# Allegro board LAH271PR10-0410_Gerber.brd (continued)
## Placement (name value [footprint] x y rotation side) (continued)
PC1231  10U_0805_25VAK  [C_0805]  234.88 144.32 90 top
PC1232  10U_0805_25VAK  [C_0805]  236.59 144.33 90 top
PC1233  0.22U_0603_25V7K  [C_0603]  232.3 142.19 270 top
PC1234  1U_0603_16V7K  [C_0603]  236.15 142.1 180 top
PC1235  2.2U_0603_10V7K  [C_0603]  237.27 140.83 90 top
PC1236  1000P_0603_50V7K  [C_0603]  236.96 133.08 90 bottom
PC1237  2200P_0402_50V7K  [C_0402]  219.74 135.14 270 top
PC1238  0.1U_0402_25V7K  [C_0402]  219.74 135.14 270 bottom
PC1239  10U_0805_25VAK  [C_0805]  222.79 135.71 270 bottom
PC1240  10U_0805_25VAK  [C_0805]  221.07 135.7 270 bottom
PC1241  10U_0805_25VAK  [C_0805]  222.79 135.71 270 top
PC1242  10U_0805_25VAK  [C_0805]  221.07 135.7 270 top
PC1243  0.22U_0603_25V7K  [C_0603]  224.53 139.71 270 top
PC1244  1U_0603_16V7K  [C_0603]  228.25 139.6 180 top
PC1245  2.2U_0603_10V7K  [C_0603]  229.35 138.34 90 top
PC1246  1000P_0603_50V7K  [C_0603]  229.11 130.62 90 bottom
PC1300  330U_D2_2.5V_R6M  [C_D2]  233.57 125.05 90 bottom
PC1301  330U_D2_2.5V_R6M  [C_D2]  241.07 125.1 90 bottom
PC1302  22U_0603_6.3VAM  [C_0603]  226.7 104.99 0 bottom
PC1303  22U_0603_6.3VAM  [C_0603]  226.7 103.77 0 bottom
PC1304  22U_0603_6.3VAM  [C_0603]  229.06 104.99 0 bottom
PC1305  22U_0603_6.3VAM  [C_0603]  229.06 103.77 0 bottom
PC1306  22U_0603_6.3VAM  [C_0603]  240.87 121.25 0 bottom
PC1307  22U_0603_6.3VAM  [C_0603]  244.11 121.25 0 bottom
PC1308  22U_0603_6.3VAM  [C_0603]  236.73 99.83 0 bottom
PC1309  22U_0603_6.3VAM  [C_0603]  240.87 122.47 0 bottom
PC1310  22U_0603_6.3VAM  [C_0603]  244.11 122.47 0 top
PC1311  22U_0603_6.3VAM  [C_0603]  237.47 122.47 0 bottom
PC1312  22U_0603_6.3VAM  [C_0603]  234.16 122.42 0 bottom
PC1313  22U_0603_6.3VAM  [C_0603]  230.76 122.42 0 bottom
PC1314  22U_0603_6.3VAM  [C_0603]  244.11 122.47 0 bottom
PC1315  22U_0603_6.3VAM  [C_0603]  237.47 122.47 0 top
PC1316  22U_0603_6.3VAM  [C_0603]  234.16 122.42 0 top
PC1317  22U_0603_6.3VAM  [C_0603]  230.76 122.42 0 top
PC1318  22U_0603_6.3VAM  [C_0603]  240.87 122.47 0 top
PC1319  22U_0603_6.3VAM  [C_0603]  228.61 99.88 0 bottom
PC1320  22U_0603_6.3VAM  [C_0603]  232.42 99.88 180 bottom
PC1321  22U_0603_6.3VAM  [C_0603]  229.06 102.55 0 bottom
PC1322  22U_0603_6.3VAM  [C_0603]  226.71 102.55 0 bottom
PC1323  22U_0603_6.3VAM  [C_0603]  233.44 99.88 0 bottom
PC1324  10U_0402_6.3VAM  [C_0402]  232 98.74 180 bottom
PC1325  10U_0402_6.3VAM  [C_0402]  227.61 98.86 180 bottom
PC1326  10U_0402_6.3VAM  [C_0402]  228.93 98.76 0 bottom
PC1327  10U_0402_6.3VAM  [C_0402]  236.37 98.74 180 bottom
PC1328  10U_0402_6.3VAM  [C_0402]  233.42 98.74 0 bottom
PC1329  10U_0402_6.3VAM  [C_0402]  237.23 98.74 0 bottom
PC1330  10U_0402_6.3VAM  [C_0402]  227.61 99.88 180 bottom
PC1331  10U_0402_6.3VAM  [C_0402]  233.51 106.05 180 bottom
PC1332  10U_0402_6.3VAM  [C_0402]  234.34 106.94 0 bottom
PC1333  10U_0402_6.3VAM  [C_0402]  234.34 106.05 0 bottom
PC1334  10U_0402_6.3VAM  [C_0402]  236.07 106.94 0 bottom
PC1335  10U_0402_6.3VAM  [C_0402]  236.07 106.05 0 bottom
PC1336  10U_0402_6.3VAM  [C_0402]  238.72 106.94 180 bottom
PC1337  10U_0402_6.3VAM  [C_0402]  238.72 106.05 180 bottom
PC1338  10U_0402_6.3VAM  [C_0402]  227.36 106.94 0 bottom
PC1339  10U_0402_6.3VAM  [C_0402]  227.36 106.05 0 bottom
PC1340  10U_0402_6.3VAM  [C_0402]  229.11 106.05 0 bottom
PC1341  10U_0402_6.3VAM  [C_0402]  229.11 106.94 0 bottom
PC1342  10U_0402_6.3VAM  [C_0402]  231.77 106.94 180 bottom
PC1343  10U_0402_6.3VAM  [C_0402]  231.77 106.05 180 bottom
PC1344  10U_0402_6.3VAM  [C_0402]  233.51 106.94 180 bottom
PC1345  1U_0201_6.3VAM  [C_0201]  227.19 97.34 180 bottom
PC1346  1U_0201_6.3VAM  [C_0201]  227.15 108.77 0 bottom
PC1347  1U_0201_6.3VAM  [C_0201]  227.15 108.21 0 bottom
PC1348  1U_0201_6.3VAM  [C_0201]  227.19 97.98 180 bottom
PC1349  1U_0201_6.3VAM  [C_0201]  227.87 97.98 0 bottom
PC1350  1U_0201_6.3VAM  [C_0201]  231.51 97.98 0 bottom
PC1351  1U_0201_6.3VAM  [C_0201]  231.51 97.34 0 bottom
PC1352  1U_0201_6.3VAM  [C_0201]  233.36 97.98 180 bottom
PC1353  1U_0201_6.3VAM  [C_0201]  233.36 97.34 180 bottom
PC1354  1U_0201_6.3VAM  [C_0201]  229.07 97.98 0 bottom
PC1355  1U_0201_6.3VAM  [C_0201]  229.07 97.34 0 bottom
PC1356  1U_0201_6.3VAM  [C_0201]  230.87 97.98 180 bottom
PC1357  1U_0201_6.3VAM  [C_0201]  230.87 97.34 180 bottom
PC1358  1U_0201_6.3VAM  [C_0201]  238.75 97.98 180 bottom
PC1359  1U_0201_6.3VAM  [C_0201]  238.75 97.34 180 bottom
PC1360  1U_0201_6.3VAM  [C_0201]  234 97.34 0 bottom
PC1361  1U_0201_6.3VAM  [C_0201]  234 97.98 0 bottom
PC1362  1U_0201_6.3VAM  [C_0201]  235.95 97.98 180 bottom
PC1363  1U_0201_6.3VAM  [C_0201]  235.92 97.36 180 bottom
PC1364  1U_0201_6.3VAM  [C_0201]  236.89 97.34 0 bottom
PC1365  1U_0201_6.3VAM  [C_0201]  236.89 97.98 0 bottom
PC1366  1U_0201_6.3VAM  [C_0201]  243.1 108.13 180 bottom
PC1367  1U_0201_6.3VAM  [C_0201]  240.73 108.77 180 bottom
PC1368  1U_0201_6.3VAM  [C_0201]  240.73 108.21 180 bottom
PC1369  1U_0201_6.3VAM  [C_0201]  241.33 108.77 0 bottom
PC1370  1U_0201_6.3VAM  [C_0201]  241.33 108.21 0 bottom
PC1371  1U_0201_6.3VAM  [C_0201]  227.87 97.34 0 bottom
PC1372  1U_0201_6.3VAM  [C_0201]  243.1 108.69 180 bottom
PC1373  1U_0201_6.3VAM  [C_0201]  238.95 108.77 0 bottom
PC1374  1U_0201_6.3VAM  [C_0201]  238.95 108.21 0 bottom
PC1375  1U_0201_6.3VAM  [C_0201]  238.37 108.77 180 bottom
PC1376  1U_0201_6.3VAM  [C_0201]  238.37 108.21 180 bottom
PC1377  1U_0201_6.3VAM  [C_0201]  236.61 108.77 0 bottom
PC1378  1U_0201_6.3VAM  [C_0201]  236.61 108.21 0 bottom
PC1379  1U_0201_6.3VAM  [C_0201]  236 108.77 180 bottom
PC1380  1U_0201_6.3VAM  [C_0201]  236 108.21 180 bottom
PC1381  1U_0201_6.3VAM  [C_0201]  233.64 108.77 180 bottom
PC1382  1U_0201_6.3VAM  [C_0201]  233.64 108.21 180 bottom
PC1383  1U_0201_6.3VAM  [C_0201]  231.87 108.77 0 bottom
PC1384  1U_0201_6.3VAM  [C_0201]  231.87 108.21 0 bottom
PC1385  1U_0201_6.3VAM  [C_0201]  231.28 108.21 180 bottom
PC1386  1U_0201_6.3VAM  [C_0201]  231.28 108.77 180 bottom
PC1387  1U_0201_6.3VAM  [C_0201]  234.25 108.21 0 bottom
PC1388  1U_0201_6.3VAM  [C_0201]  234.25 108.77 0 bottom
PC1389  1U_0201_6.3VAM  [C_0201]  229.51 108.21 0 bottom
PC1390  1U_0201_6.3VAM  [C_0201]  229.51 108.77 0 bottom
PC1391  1U_0201_6.3VAM  [C_0201]  228.92 108.77 180 bottom
PC1392  1U_0201_6.3VAM  [C_0201]  228.92 108.21 180 bottom
PC1393  330U_D2_2.5V_R6M  [C_D2]  225.47 122.6 90 bottom
PC1394  330U_D2_2.5V_R6M  [C_D2]  241.63 105.18 270 bottom
PC1395  22U_0603_6.3VAM  [C_0603]  230.77 121.19 0 bottom
PC1396  22U_0603_6.3VAM  [C_0603]  234.16 121.19 0 bottom
PC1397  22U_0603_6.3VAM  [C_0603]  237.48 121.24 0 bottom
PC1398  22U_0603_6.3VAM  [C_0603]  234.15 119.98 0 bottom
PC1399  22U_0603_6.3VAM  [C_0603]  237.51 119.97 0 bottom
PC1400  22U_0603_6.3VAM  [C_0603]  240.88 120.01 0 bottom
PC1401  10U_0402_6.3VAM  [C_0402]  235.77 102.34 0 bottom
PC1402  10U_0402_6.3VAM  [C_0402]  233.6 101.5 0 bottom
PC1403  10U_0402_6.3VAM  [C_0402]  235.79 101.42 0 bottom
PC1404  10U_0402_6.3VAM  [C_0402]  227.58 100.83 180 bottom
PC1405  10U_0402_6.3VAM  [C_0402]  232.76 101.5 180 bottom
PC1406  10U_0402_6.3VAM  [C_0402]  238.79 101.4 180 bottom
PC1407  10U_0402_6.3VAM  [C_0402]  232.76 102.41 180 bottom
PC1408  10U_0402_6.3VAM  [C_0402]  235.78 103.25 0 bottom
PC1409  10U_0402_6.3VAM  [C_0402]  233.6 102.4 0 bottom
PC1410  10U_0402_6.3VAM  [C_0402]  232.77 104.24 180 bottom
PC1411  10U_0402_6.3VAM  [C_0402]  235.77 104.16 0 bottom
PC1412  10U_0402_6.3VAM  [C_0402]  238.77 102.33 180 bottom
PC1413  10U_0402_6.3VAM  [C_0402]  238.79 103.24 180 bottom
PC1414  10U_0402_6.3VAM  [C_0402]  235.78 105.07 0 bottom
PC1415  10U_0402_6.3VAM  [C_0402]  238.77 104.16 180 bottom
PC1416  10U_0402_6.3VAM  [C_0402]  233.58 105.14 0 bottom
PC1417  10U_0402_6.3VAM  [C_0402]  232.76 105.13 180 bottom
PC1418  10U_0402_6.3VAM  [C_0402]  238.78 105.06 180 bottom
PC1419  10U_0402_6.3VAM  [C_0402]  233.59 104.23 0 bottom
PC1420  10U_0402_6.3VAM  [C_0402]  233.59 103.31 0 bottom
PC1421  10U_0402_6.3VAM  [C_0402]  232.77 103.32 180 bottom
PC1500  470U_X_2VM_R6M  [C_X]  254.8 122.91 0 bottom
PC1502  22U_0603_6.3VAM  [C_0603]  253.09 106.73 180 bottom
PC1503  22U_0603_6.3VAM  [C_0603]  253.08 105.52 180 bottom
PC1504  22U_0603_6.3VAM  [C_0603]  253.09 104.31 180 bottom
PC1505  22U_0603_6.3VAM  [C_0603]  249.34 100.62 0 bottom
PC1506  22U_0603_6.3VAM  [C_0603]  246.02 106.73 180 bottom
PC1507  22U_0603_6.3VAM  [C_0603]  246.02 105.52 180 bottom
PC1508  22U_0603_6.3VAM  [C_0603]  246.02 104.31 180 bottom
PC1509  22U_0603_6.3VAM  [C_0603]  246.99 106.73 0 bottom
PC1510  22U_0603_6.3VAM  [C_0603]  246.99 105.52 0 bottom
PC1511  22U_0603_6.3VAM  [C_0603]  246.99 104.31 0 bottom
PC1512  22U_0603_6.3VAM  [C_0603]  250.74 104.31 180 bottom
PC1513  22U_0603_6.3VAM  [C_0603]  250.74 105.52 180 bottom
PC1514  22U_0603_6.3VAM  [C_0603]  250.74 106.73 180 bottom
PC1515  10U_0402_6.3VAM  [C_0402]  247.3 108.68 180 bottom
PC1516  10U_0402_6.3VAM  [C_0402]  247.3 107.77 180 bottom
PC1517  10U_0402_6.3VAM  [C_0402]  248.14 108.68 0 bottom
PC1518  10U_0402_6.3VAM  [C_0402]  248.14 107.78 0 bottom
PC1519  10U_0402_6.3VAM  [C_0402]  253.15 107.77 180 bottom
PC1520  10U_0402_6.3VAM  [C_0402]  253.15 108.67 180 bottom
PC1521  10U_0402_6.3VAM  [C_0402]  249.29 98.41 0 bottom
PC1522  10U_0402_6.3VAM  [C_0402]  251.96 98.41 180 bottom
PC1523  10U_0402_6.3VAM  [C_0402]  249.29 97.47 0 bottom
PC1524  10U_0402_6.3VAM  [C_0402]  251.96 97.47 180 bottom
PC1525  1U_0201_6.3VAM  [C_0201]  244.5 108.7 180 bottom
PC1526  1U_0201_6.3VAM  [C_0201]  244.5 108.14 180 bottom
PC1527  1U_0201_6.3VAM  [C_0201]  245.1 108.84 0 bottom
PC1528  1U_0201_6.3VAM  [C_0201]  245.1 108.27 0 bottom
PC1529  1U_0201_6.3VAM  [C_0201]  250.34 108.79 180 bottom
PC1530  1U_0201_6.3VAM  [C_0201]  250.34 108.22 180 bottom
PC1531  1U_0201_6.3VAM  [C_0201]  250.94 108.79 0 bottom
PC1532  1U_0201_6.3VAM  [C_0201]  250.94 108.22 0 bottom
PC1533  1U_0201_6.3VAM  [C_0201]  245.52 97.63 180 bottom
PC1534  1U_0201_6.3VAM  [C_0201]  246.16 97.63 0 bottom
PC1535  1U_0201_6.3VAM  [C_0201]  249.34 99.4 0 bottom
PC1536  1U_0201_6.3VAM  [C_0201]  253.09 100.62 180 bottom
PC1600  22U_0603_6.3VAM  [C_0603]  226.21 107.92 270 bottom
PC1601  22U_0603_6.3VAM  [C_0603]  220.72 119.67 90 bottom
PC1602  22U_0603_6.3VAM  [C_0603]  211.98 125.18 180 bottom
PC1603  22U_0603_6.3VAM  [C_0603]  211.99 123.97 180 bottom
PC1604  22U_0603_6.3VAM  [C_0603]  221.95 119.68 90 bottom
PC1605  22U_0603_6.3VAM  [C_0603]  211.98 122.77 180 bottom
PC1606  22U_0603_6.3VAM  [C_0603]  211.98 125.48 180 top
PC1607  22U_0603_6.3VAM  [C_0603]  211.99 124.28 180 top
PC1608  22U_0603_6.3VAM  [C_0603]  211.98 123.07 180 top
PC1609  22U_0603_6.3VAM  [C_0603]  219.49 119.66 90 bottom
PC1610  10U_0402_6.3VAM  [C_0402]  223.72 108.83 0 bottom
PC1611  10U_0402_6.3VAM  [C_0402]  226.38 108.83 180 bottom
PC1612  10U_0402_6.3VAM  [C_0402]  224.28 107.94 0 bottom
PC1613  10U_0402_6.3VAM  [C_0402]  211.82 120.02 180 top
PC1614  10U_0402_6.3VAM  [C_0402]  211.83 121.94 180 top
PC1615  10U_0402_6.3VAM  [C_0402]  211.82 120.98 180 top
PC1616  10U_0402_6.3VAM  [C_0402]  211.81 119.08 180 top
PC1617  1U_0201_6.3VAM  [C_0201]  223.04 108.35 270 bottom
PC1700  2200P_0402_50V7K  [C_0402]  268.33 122.91 180 bottom
PC1701  0.1U_0402_25V7K  [C_0402]  268.33 122.91 180 top
PC1702  10U_0603_25V6M  [C_0603]  268.76 121.84 180 top
PC1703  10U_0603_25V6M  [C_0603]  268.76 121.84 180 bottom
PC1704  10U_0603_25V6M  [C_0603]  268.74 120.61 180 top
PC1705  10U_0603_25V6M  [C_0603]  268.74 120.61 180 bottom
PC1706  0.22U_0603_25V7K  [C_0603]  272.24 125.95 180 bottom
PC1707  1U_0603_16V7K  [C_0603]  272.06 129.73 270 bottom
PC1708  2.2U_0603_10V7K  [C_0603]  270.74 130.75 90 bottom
PC1709  1000P_0603_50V7K  [C_0603]  262.97 126 270 bottom
PC1710  10U_0603_25V6M  [C_0603]  271.25 121.78 0 bottom
PC1711  10U_0603_25V6M  [C_0603]  271.2 123.04 0 bottom
PC1712  10U_0603_25V6M  [C_0603]  271.18 124.31 0 bottom
PC1713  10U_0603_25V6M  [C_0603]  269.18 124.18 180 bottom
PC1800  2200P_0402_50V7K  [C_0402]  208.8 130.74 270 top
PC1801  0.1U_0402_25V7K  [C_0402]  208.8 130.74 270 bottom
PC1802  10U_0805_25VAK  [C_0805]  210.11 131.03 270 bottom
PC1803  10U_0805_25VAK  [C_0805]  210.12 131.02 270 top
PC1804  10U_0805_25VAK  [C_0805]  211.86 131 270 top
PC1805  10U_0805_25VAK  [C_0805]  211.85 131.01 270 bottom
PC1806  0.22U_0603_25V7K  [C_0603]  214.26 133.8 270 bottom
PC1807  1U_0603_16V7K  [C_0603]  218.04 132.32 180 bottom
PC1808  2.2U_0603_10V7K  [C_0603]  218.22 129.85 90 bottom
PC1809  1000P_0603_50V7K  [C_0603]  218.39 128.22 270 bottom
PC2100  0.022U_0402_25V7K  [C_0402]  38.32 18.64 270 bottom
PC2102  0.022U_0402_25V7K  [C_0402]  38.2 21.39 270 bottom
PC2103  0.1U_0402_25V6  [C_0402]  39.19 10.34 270 top
PD4  -  [SS5P10-M3-86A_TO277A3]  47.93 10.93 180 top
PD6  -  [SS5P10-M3-86A_TO277A3]  47.95 10.91 0 bottom
PD8  -  [BAS40CW_SOT323-3]  339.85 8.2 180 bottom
PD9  AZ5A25-02R_SOT523-3  [TVNST52302AB0_SOT523-3]  263.6 9.58 180 top
PD10  AZ5A25-02R_SOT523-3  [TVNST52302AB0_SOT523-3]  260.66 7.89 270 top
PD12  BAT54CW-7-F SOT-323  [BAT54CW_SOT323-3]  56.55 14.95 270 top
PD13  BAT54CW-7-F SOT-323  [BAT54CW_SOT323-3]  51.46 14.95 90 top
PD14  BAT54CW-7-F SOT-323  [BAT54CW_SOT323-3]  46.6 25.52 90 top
PD15  BAT54CW-7-F SOT-323  [BAT54CW_SOT323-3]  53.82 9.41 90 bottom
PD200  30MA_30V_0.5UA_0.4V_SOD323-2  [D_SOD323-2]  203.37 6.52 0 top
PD700  BAT54CW-7-F SOT-323  [BAT54CW_SOT323-3]  282.56 36.75 180 top
PD701  BAT54CW-7-F SOT-323  [BAT54CW_SOT323-3]  283.83 40.57 270 top
PD702  -  [MM3Z22VST1G_SOD323-2]  293.07 28.91 270 top
PH1100  100K_0402_1%_TSM0B104F4251RZ  [R_0402]  216.26 120.61 0 top
PH1101  220K_0402_5%_ERTJ0EV224J  [R_0402]  253.45 131.2 90 top
PH1102  220K_0402_5%_ERTJ0EV224J  [R_0402]  261.97 133.23 0 bottom
PH1103  220K_0402_5%_ERTJ0EV224J  [R_0402]  253.72 134.84 90 top
PH1104  220K_0402_5%_ERTJ0EV224J  [R_0402]  265.97 132.03 0 bottom
PJP1  PAD-OPEN1x1m  [JUMP_43X39]  191.42 85.84 90 top
PJP2  PAD-OPEN1x1m  [JUMP_43X39]  191.99 97.31 270 top
PJP3  -  [JUMP_43X79]  199.03 20.6 0 bottom
PJP5  -  [JUMP_43X79]  42.19 30.65 0 top
PJP6  PAD-OPEN1x1m  [JUMP_43X39]  36.57 46.4 180 top
PJP12  PAD-OPEN1x1m  [JUMP_43X39]  96.71 22.76 0 top
PJP17  PAD-OPEN1x2m  [JUMP_43X79]  342.88 36.28 270 top
PJP18  PAD-OPEN1x1m  [JUMP_43X39]  333.94 19.96 90 top
PJP19  PAD-OPEN1x1m  [JUMP_43X39]  356.9 22.6 90 top
PJP20  PAD-OPEN1x1m  [JUMP_43X39]  132.03 14.11 90 top
PJP22  PAD-OPEN1x1m  [JUMP_43X39]  144.86 20.61 180 top
PJP30  -  [JUMP_43X79]  91.4 31.69 270 top
PJP32  PAD-OPEN1x1m  [JUMP_43X39]  326.06 30.91 180 top
PJP35  PAD-OPEN1x1m  [JUMP_43X39]  276.4 3.22 90 top
PJP36  -  [JUMP_43X79]  320.76 25.76 0 top
PJP37  -  [JUMP_43X79]  329.96 23.26 180 top
PJP38  -  [JUMP_43X79]  109.37 27.11 180 bottom
PJP39  -  [JUMP_43X79]  345.48 45.5 180 top
PJP40  PAD-OPEN 4x4m  [JUMP_43X118]  334.04 45.9 0 top
PJP42  -  [JUMP_43X79]  335.99 23.95 180 bottom
PJP43  -  [JUMP_43X79]  184.42 92.04 270 bottom
PJP62  -  [JUMP_43X79]  313.14 14.17 0 top
PJP64  -  [JUMP_43X79]  89.97 21.94 90 top
PJP65  -  [JUMP_43X79]  185.03 82.62 90 bottom
PJP66  -  [JUMP_43X79]  179.58 70.21 0 bottom
PJP67  -  [JUMP_43X118]  104.15 12.5 90 top
PJP69  PAD-OPEN1x2m  [JUMP_43X79]  34.37 12.96 180 bottom
PJP100  PAD-OPEN 1x2m~D  [JUMP_43X79]  116.81 2.72 90 top
PJP101  -  [JUMP_43X118]  97.1 6.33 90 top
PJP102  PAD-OPEN 1x2m~D  [JUMP_43X79]  73.4 11.39 180 bottom
PJP103  -  [JUMP_43X118]  61.07 16.46 180 top
PJP200  PAD-OPEN 1x2m  [JUMP_43X79]  213.84 5.52 90 top
PJP202  JUMP_1x3m  [JUMP_43X118]  245.57 10.25 270 top
PJP203  JUMP_1x3m  [JUMP_43X118]  240.34 10.27 270 top
PJP204  PAD-OPEN1x1m  [JUMP_43X39]  207.91 12.84 180 top
PJP300  -  [JUMP_43X79]  278.34 98.72 270 bottom
PJP301  -  [JUMP_43X118]  268.79 105.62 180 bottom
PJP391  PAD-OPEN1x1m  [JUMP_43X39]  113.88 27.92 90 top
PJP400  -  [JUMP_43X79]  286.72 42.01 90 top
PJP401  -  [JUMP_43X79]  285.96 54.89 90 top
PJP500  PAD-OPEN 1x2m~D  [JUMP_43X79]  315.4 32.84 90 top
PJP501  -  [JUMP_43X118]  295.94 38.53 180 top
PJP502  -  [JUMP_43X118]  297.33 29.04 180 top
PJP503  PAD-OPEN 1x2m~D  [JUMP_43X79]  315.26 24.1 90 top
PJP700  PAD-OPEN 43x118  [JUMP_43X118-NPM]  308.51 21.13 0 top
PJP701  PAD-OPEN1x1m  [JUMP_43X39]  282.92 34.85 180 top
PJP800  PAD-OPEN 1x2m  [JUMP_43X79]  142.08 3.23 0 top
PJP801  PAD-OPEN 43x118  [JUMP_43X118]  160.39 12.84 90 top
PJP900  PAD-OPEN1x1m  [JUMP_43X39]  123.1 3.37 0 top
PJP901  PAD-OPEN1x1m  [JUMP_43X39]  136.7 3.68 0 top
PL5  -  [5A_Z80_0805_2P]  12.94 35.42 270 bottom
PL6  -  [5A_Z80_0805_2P]  11.12 36.26 270 bottom
PL7  -  [5A_Z80_0805_2P]  22.77 56.64 315 top
PL8  -  [5A_Z80_0805_2P]  21.48 55.38 315 top
PL9  9A Z80 10M 1812_2P  [9A_Z80_1812_2P]  88.59 4.54 90 top
PL11  FBMJ4516HS720NT_2P  [TAIYO_FBMJ4516HS720NT_2P]  267.13 7.04 0 top
PL12  FBMJ4516HS720NT_2P  [TAIYO_FBMJ4516HS720NT_2P]  267.13 9.46 0 top
PL100  1.5UH_9A_20%_7X7X3_M  [L_7X7X3_M_2P]  108.2 7.3 180 top
PL101  2.2UH_7.8A_20%_7X7X3_M  [L_7X7X3_M_2P]  71.34 16.76 180 top
PL201  0.68UH_PCMC063T-R68MN_15.5A_20%  [CYNTE_PCMC063T-R68MN_2P]  235.71 5.99 180 top
PL300  1UH_6.6A_20%_5X5X3_M  [L_5X5X3_M_2P]  273.15 102.92 90 bottom
PL400  1UH_PCMB042T-1R0MS_4.5A_20%  [CYNTE_PCMB042T-1R0MS_2P]  285.68 49.03 90 top
PL500  2.2UH_7.8A_20%_7X7X3_M  [L_7X7X3_M_2P]  305.28 38.69 180 top
PL501  1.5UH_9A_20%_7X7X3_M  [L_7X7X3_M_2P]  306.6 28.94 180 top
PL700  1UH_6.6A_20%_5X5X3_M  [L_5X5X3_M_2P]  306.88 21.13 0 top
PL701  2.2UH_7.8A_20%_7X7X3_M  [L_7X7X3_M_2P]  291.44 22.42 270 top
PL801  1.5UH_MMD-06CZ-1R5M-V1_9A_20%  [L_7X7X3_M_2P]  151.04 5.44 0 top
PL900  1UH_PCMB042T-1R0MS_4.5A_20%  [CYNTE_PCMB042T-1R0MS_2P]  131.31 4.58 0 top
PL1200  -  [5A_Z80_0805_2P]  274.03 133.84 180 bottom
PL1201  -  [5A_Z80_0805_2P]  274.03 135.74 180 bottom
PL1202  0.15UH_PCME064T-R15MS_36A_20%  [L_7X7X4_M]  249.14 131.76 270 top
PL1203  0.15UH_PCME064T-R15MS_36A_20%  [L_7X7X4_M]  241.39 131.72 270 top
PL1204  0.15UH_PCME064T-R15MS_36A_20%  [L_7X7X4_M]  233.64 131.71 270 top
PL1205  0.15UH_PCME064T-R15MS_36A_20%  [L_7X7X4_M]  225.9 129.2 270 top
PL1700  0.15UH_PCME064T-R15MS_36A_20%  [L_7X7X4_M]  261.57 129.01 180 bottom
PL1800  0.47UH_MMD05CZR47M_12A_20%  [MAG_MMD05CZR47M_4P]  219.08 123.92 180 top
PQ4  L2N7002DW1T1G_SC88-6  [DMN65D8LDW-7_SOT363-6]  47.32 23.74 180 top
PQ5  L2N7002DW1T1G_SC88-6  [DMN65D8LDW-7_SOT363-6]  54.63 18.14 270 top
PQ6  L2N7002DW1T1G_SC88-6  [DMN65D8LDW-7_SOT363-6]  57.77 22.82 90 top
PQ7  L2N7002DW1T1G_SC88-6  [DMN65D8LDW-7_SOT363-6]  55.89 20.07 270 bottom
PQ8  L2N7002DW1T1G_SC88-6  [DMN65D8LDW-7_SOT363-6]  52 11.62 90 bottom
PQ9  L2N7002DW1T1G_SC88-6  [DMN65D8LDW-7_SOT363-6]  55.4 25.23 270 bottom
PQ17  AOSP21357L_SO8  [Q_P_SO8]  44.41 22.16 180 top
PQ18  AOSP21357L_SO8  [Q_P_SO8]  40.64 9.41 0 top
PQ19  -  [EMB80P03JS_SOT-23-3]  51.19 24.02 180 top
PQ20  -  [EMB80P03JS_SOT-23-3]  47.69 17.57 270 top
PQ22  AOSP21357L_SO8  [Q_P_SO8]  40.59 22.16 0 bottom
PQ23  AOSP21357L_SO8  [Q_P_SO8]  44.45 9.41 180 bottom
PQ24  -  [EMB80P03JS_SOT-23-3]  49.6 25.33 0 bottom
PQ25  -  [EMB80P03JS_SOT-23-3]  56.11 16.11 270 bottom
PQ26  -  [L2N7002WT1G_SC70-3]  147.74 24.44 270 top
PQ200  AON6380_DFN5X6-8-5  [Q_N_DFN56-8-5]  216.85 3.1 0 top
PQ201  AON6314_DFN5X6-8  [Q_N_DFN56-8-5]  226.66 8.65 180 top
PQ700  SI7149DP-T1-GE3_POWERPAKSO8-5  [Q_P_DFN56-8-5]  57.07 8.78 90 top
PQ701  AONS32306_DFN5X6-8-5  [Q_N_DFN56-8-5]  307.13 11.84 0 top
PQ702  AON6380_DFN5X6-8-5  [Q_N_DFN56-8-5]  296.24 24.1 270 top
PQ703  AON6314_DFN5X6-8  [Q_N_DFN56-8-5]  301.57 14.28 90 top
PQ704  L2N7002DW1T1G_SC88-6  [DMN66D0LDW-7_SOT363-6]  282.67 21.79 270 top
PQ705  -  [EMB80P03JS_SOT-23-3]  60.18 14.76 0 bottom
PQ800  AON7408L_DFN8-5  [Q_N_DFN33-8-5]  148.15 3.17 90 top
PQ801  AON7752_DFN3X3EP8-5  [Q_N_DFN33-8-5]  145.28 9.3 270 top
PQ2100  EMB12P03V_EDFN8-5  [Q_P_DFN33-8-5]  36.5 16.37 0 bottom
PQ2101  -  [EMB80P03JS_SOT-23-3]  36.26 14.29 180 top
PQ2102  L2N7002DW1T1G_SC88-6  [DMN65D8LDW-7_SOT363-6]  35.92 8.07 90 top
PQ2104  EMB12P03V_EDFN8-5  [Q_P_DFN33-8-5]  36.83 22.69 270 bottom
PQ2105  -  [EMB80P03JS_SOT-23-3]  37.29 22.46 180 top
PQ2106  L2N7002DW1T1G_SC88-6  [DMN65D8LDW-7_SOT363-6]  38.24 16.18 90 top
PR25  100K_0402_5%  [R_0402]  50.22 19.99 180 top
PR26  100K_0402_5%  [R_0402]  52.64 17.56 270 top
PR27  100K_0402_5%  [R_0402]  14.33 32.68 90 bottom
PR28  1M_0402_5%  [R_0402]  54.9 21.8 90 top
PR29  330K_0402_5%  [R_0402]  52.63 18.4 90 top
PR31  100K_0402_5%  [R_0402]  48.47 19.97 90 top
PR32  100K_0402_5%  [R_0402]  53.54 16.63 90 top
PR33  1M_0402_5%  [R_0402]  53.66 23.16 90 top
PR34  10K_0402_5%  [R_0402]  58.7 20.07 90 top
PR35  0_0402_5%  [R0402_0OHM]  45.53 24.82 90 top
PR36  0_0402_5%  [R0402_0OHM]  45.85 20.01 90 top
PR38  0_0402_5%  [R0402_0OHM]  57.83 20.96 180 top
PR39  100K_0402_5%  [R_0402]  44.66 25.79 270 top
PR40  100K_0402_5%  [R_0402]  46.71 20.02 0 top
PR41  0_0402_5%  [R0402_0OHM]  47.63 20.91 180 top
PR42  221K_0402_1%~D  [R_0402]  59.67 22.64 90 top
PR43  100K_0402_5%  [R_0402]  48.53 21.49 0 bottom
PR44  100K_0402_5%  [R_0402]  50.47 17.67 270 bottom
PR45  100K_0402_5%  [R_0402]  26.12 54.14 315 top
PR46  1M_0402_5%  [R_0402]  47.01 20.75 90 bottom
PR47  330K_0402_5%  [R_0402]  52.25 17.67 270 bottom
PR48  100K_0402_5%  [R_0402]  50.27 21.49 0 bottom
PR50  100K_0402_5%  [R_0402]  52.3 14.24 180 bottom
PR51  1M_0402_5%  [R_0402]  52.07 25.67 270 bottom
PR52  10K_0402_5%  [R_0402]  57.86 16.13 90 bottom
PR53  0_0402_5%  [R0402_0OHM]  52.07 23.92 270 bottom
PR54  0_0402_5%  [R0402_0OHM]  53.03 18.52 180 bottom
PR55  0_0402_5%  [R0402_0OHM]  56.9 19.27 90 bottom
PR57  100K_0402_5%  [R_0402]  56.91 17.53 90 bottom
PR58  221K_0402_1%~D  [R_0402]  54.13 21.44 0 bottom
PR59  100K_0402_5%  [R_0402]  53.03 19.41 180 bottom
PR60  0_0402_5%  [R0402_0OHM]  52.12 20.3 0 bottom
PR61  1K_0402_5%  [R_0402]  338.16 9.06 90 bottom
PR62  100K_0402_5%  [R_0402]  262.08 10.35 270 top
PR64  10M_0402_5%  [R_0402]  150.76 23.85 90 top
PR65  100_0402_5%  [R_0402]  263.42 6.97 90 top
PR66  100_0402_5%  [R_0402]  262.46 6.97 90 top
PR67  100_0402_5%  [R_0402]  261.59 6.96 90 top
PR71  100K_0402_5%  [R_0402]  57.51 17.38 90 top
PR72  100K_0402_5%  [R_0402]  55.18 12.35 270 bottom
PR75  100K_0402_5%  [R_0402]  57.83 20.08 180 top
PR76  100K_0402_5%  [R_0402]  52.06 22.17 270 bottom
PR100  4.7_1206_5%  [R_1206]  107.92 2.49 180 top
PR101  0_0603_5%  [R0603_0OHM]  111.92 4.41 270 top
PR102  0_0402_5%  [R0402_0OHM]  115.39 10.33 0 top
PR103  0_0402_5%  [R_0402]  115.38 11.21 0 top
PR104  0_0402_5%  [R0402_0OHM]  110.77 10.11 0 bottom
PR105  0_0402_5%  [R0402_0OHM]  110.77 11.02 0 bottom
PR106  1K_0402_5%  [R_0402]  111.77 11.23 270 top
PR107  100K_0402_5%  [R_0402]  116.3 9.44 180 top
PR108  499K_0402_1%  [R_0402]  113.6 10.32 90 top
PR109  499K_0402_1%  [R_0402]  114.51 10.32 90 top
PR110  100K_0402_5%  [R_0402]  67.4 9.3 90 bottom
PR111  0_0603_5%  [R0603_0OHM]  71.65 14.08 0 bottom
PR112  4.7_1206_5%  [R_1206]  72.17 21.49 180 top
PR113  0_0402_5%  [R0402_0OHM]  65.61 10.69 0 bottom
PR114  1K_0402_5%  [R_0402]  63.64 13.39 90 bottom
PR115  1M_0402_1%  [R_0402]  65.86 11.53 180 bottom
PR200  2.2_0603_5%  [R_0603]  208.69 10 180 top
PR201  6.19K_0402_1%  [R_0402]  207.06 6.15 90 top
PR202  4.7_1206_5%  [R_1206]  229.35 10.48 0 top
PR203  5.1_0603_5%  [R_0603]  200.65 6.71 90 top
PR204  2.2_0603_5%  [R_0603]  201.87 8.11 270 top
PR205  100K_0402_1%  [R_0402]  199.41 9.45 0 top
PR206  13K_0402_1%  [R_0402]  200.46 14.85 0 top
PR207  475K_0402_1%  [R_0402]  199.41 10.32 0 top
PR208  200K_0402_5%  [R_0402]  199.41 12.09 0 top
PR209  20K_0402_1%  [R_0402]  200.34 13.96 180 top
PR210  100K_0402_5%  [R_0402]  199.43 12.97 0 top
PR300  100K_0402_1%  [R_0402]  273.47 99.69 270 top
PR301  4.7_1206_5%  [R_1206]  277.17 103.15 90 bottom
PR302  2.2_0603_5%  [R_0603]  276.65 100.63 0 bottom
PR303  100_0402_1%  [R_0402]  268.73 102.35 270 bottom
PR304  0_0402_5%  [R0402_0OHM]  268.34 96 0 top
PR306  0_0402_5%  [R0402_0OHM]  267.82 101.75 180 bottom
PR307  1M_0402_1%  [R_0402]  269.25 96.96 180 top
PR308  0_0402_5%  [R_0402]  269.95 100.37 180 bottom
PR309  0_0402_5%  [R0402_0OHM]  269.04 99.42 0 bottom
PR310  0_0402_5%  [R0402_0OHM]  267.82 100.85 180 bottom
PR311  10K_0402_1%  [R_0402]  272.56 98.77 90 top
PR312  10K_0402_1%  [R_0402]  272.56 97.01 90 top
PR313  10K_0402_1%  [R_0402]  271.62 99.69 270 top
PR314  10K_0402_1%  [R_0402]  269.94 97.97 180 bottom
PR400  100K_0402_5%  [R_0402]  284.23 42.15 90 top
PR401  0_0402_5%  [R0402_0OHM]  282.93 47.67 180 top
PR402  1M_0402_5%  [R_0402]  282.94 48.56 180 top
PR403  4.7_0603_5%  [R_0603]  288.48 49.27 90 top
PR404  36.5K_0402_1%  [R_0402]  281.84 45.6 0 top
PR405  11.5K_0402_1%  [R_0402]  282.75 44.72 180 top
PR500  100K_0402_5%  [R_0402]  312.53 41.06 270 top
PR501  0_0603_5%  [R0603_0OHM]  309.05 35.82 270 top
PR502  4.7_1206_5%  [R_1206]  302.25 43.48 180 top
PR505  0_0402_5%  [R0402_0OHM]  312.44 31.94 180 top
PR506  1K_0402_5%  [R_0402]  310.18 43.58 270 top
PR507  1M_0402_1%  [R_0402]  311.53 32.82 0 top
PR508  0_0402_5%  [R_0402]  314.71 30.26 90 top
PR509  0_0402_5%  [R_0402]  313.4 40.15 90 top
PR510  499K_0402_1%  [R_0402]  312.37 43.39 0 top
PR511  4.7_1206_5%  [R_1206]  305.94 33.71 180 top
PR512  499K_0402_1%  [R_0402]  312.38 42.36 0 top
PR513  1K_0402_5%  [R_0402]  309.7 33.14 270 top
PR514  0_0603_5%  [R0603_0OHM]  310.66 26.12 270 top
PR515  100K_0402_5%  [R_0402]  313.84 31.17 270 top
PR700  0.005_1206_1%  [R_1206_4P-D]  58.86 12.46 0 top
PR701  4.02K_0402_1%  [R_0402]  284.51 25.78 270 top
PR702  100_0402_1%  [R_0402]  60.93 10.92 180 top
PR703  0_0402_5%  [R0402_0OHM]  59.84 9.98 270 top
PR704  0_0402_5%  [R0402_0OHM]  61.15 9.98 270 top
PR705  10_1206_5%  [R_1206]  284.6 38.08 0 top
PR706  274K_0402_1%  [R_0402]  285.83 34.98 90 top
PR707  4.12K_0603_1%  [R_0603]  289.57 35.83 270 top
PR708  2.2_0603_5%  [R_0603]  291.76 30.36 0 top
PR709  49.9K_0402_1%  [R_0402]  286.72 34.13 180 top
PR710  0_0402_5%  [R0402_0OHM]  282.67 29.81 0 top
PR711  0_0402_5%  [R0402_0OHM]  282.67 28.95 0 top
PR712  100K_0402_1%  [R_0402]  289.37 36.78 180 top
PR713  0_0402_5%  [R0402_0OHM]  288.57 34.12 180 top
PR714  0_0402_5%  [R0402_0OHM]  282.67 31.54 0 top
PR715  0.01_1206_1%  [R_1206_4P-D]  287.14 15.22 180 top
PR716  121K_0402_1%  [R_0402]  288.52 35.07 180 top
PR717  0_0402_5%  [R0402_0OHM]  285.01 35.9 270 top
PR718  0_0402_5%  [R0402_0OHM]  282.67 30.68 0 top
PR719  0_0402_5%  [R0402_0OHM]  283.06 32.4 0 top
PR720  20K_0402_1%  [R_0402]  283.2 22.85 180 top
PR721  3.92K_0402_1%  [R_0402]  284.02 22.86 0 top
PR722  4.7_1206_5%  [R_1206]  299.52 12.21 0 top
PR723  24.9K_0402_1%  [R_0402]  281.69 31.5 90 top
PR724  0_0402_5%  [R0402_0OHM]  282.59 25.04 90 top
PR725  10K_0402_5%  [R_0402]  283.46 25.96 270 top
PR726  2.74K_0402_1%  [R_0402]  281.73 21.96 270 top
PR727  10_0402_1%  [R_0402]  287.29 25.03 90 top
PR728  10_0402_1%  [R_0402]  286.43 25.03 90 top
PR729  0_0402_5%  [R_0402]  283.59 27.22 180 top
PR730  100K_0402_1%  [R_0402]  283.59 28.08 180 top
PR731  1M_0402_5%  [R_0402]  57.76 11.84 90 bottom
PR732  1M_0402_5%  [R_0402]  57.75 13.59 90 bottom
PR733  100K_0402_5%  [R_0402]  58.61 10.55 0 bottom
PR734  100K_0402_5%  [R_0402]  60.57 10.55 270 bottom
PR735  10_0402_1%  [R_0402]  308.4 15.1 180 bottom
PR800  100K_0402_5%  [R_0402]  153.88 9.64 180 top
PR801  118K_0402_1%  [R_0402]  157.36 10.28 180 top
PR802  2.2_0603_5%  [R_0603]  149.95 10.93 180 top
PR803  499_0402_1%  [R_0402]  154.83 11.81 270 bottom
PR804  470K_0402_1%  [R_0402]  156.39 14.65 0 top
PR805  4.7_1206_5%  [R_1206]  146.19 11.31 180 top
PR807  4.99K_0402_1%  [R_0402]  156.4 12.91 0 top
PR808  10K_0402_1%  [R_0402]  156.4 12.04 0 top
PR809  10_0402_1%  [R_0402]  157.32 13.77 180 top
PR810  0_0402_5%  [R0402_0OHM]  156.73 11.65 180 bottom
PR811  0_0402_5%  [R0402_0OHM]  154.83 10.04 0 bottom
PR812  0_0402_5%  [R_0402]  155.62 9.64 180 top
PR900  100K_0402_5%  [R_0402]  124.51 5.59 0 top
PR901  0_0402_5%  [R0402_0OHM]  128.91 7.27 90 top
PR902  1M_0402_5%  [R_0402]  130.67 7.27 90 top
PR903  4.7_0603_5%  [R_0603]  131.7 7.43 0 top
PR904  200K_0402_1%  [R_0402]  126.49 8.19 270 top
PR905  100K_0402_1%  [R_0402]  125.61 7.27 90 top
PR906  0_0402_5%  [R0402_0OHM]  121.63 5.59 0 top
PR1100  100_0402_1%  [R_0402]  225.84 117.73 270 top
PR1101  12K_0402_1%  [R_0402]  263.02 151.22 270 bottom
PR1102  7.5K_0603_1%  [R_0603]  218.07 121.88 90 bottom
PR1103  499_0402_1%  [R_0402]  268.5 150.09 90 bottom
PR1104  45.3_0402_1%  [R_0402]  265.84 150.1 90 bottom
PR1105  100_0402_1%  [R_0402]  267.62 151.02 270 bottom
PR1106  0_0402_5%  [R0402_0OHM]  253.71 151.57 0 top
PR1107  1K_0402_5%  [R_0402]  256.37 151.57 0 top
PR1108  0_0402_5%  [R0402_0OHM]  253.71 150.68 0 top
PR1109  1.65K_0402_1%  [R_0402]  256.37 150.68 0 top
PR1110  100_0402_1%  [R_0402]  268.5 150.09 90 top
PR1111  100_0402_1%  [R_0402]  224.9 117.72 270 top
PR1112  29.4K_0402_1%  [R_0402]  262.76 147.46 90 bottom
PR1113  10_0402_1%  [R_0402]  267.13 150.03 90 top
PR1114  10K_0402_1%  [R_0402]  263.89 151.23 270 top
PR1115  0_0402_5%  [R0402_0OHM]  266.23 150.03 90 top
PR1116  12.4K_0402_1%  [R_0402]  260.33 151.23 270 top
PR1117  49.9_0402_1%  [R_0402]  265.34 150.02 90 top
PR1118  1.5K_0402_1%  [R_0402]  258.48 151.9 270 top
PR1119  100_0402_1%  [R_0402]  240.68 118.21 270 top
PR1120  37.4K_0402_1%  [R_0402]  264.92 148.42 270 bottom
PR1121  0_0402_5%  [R0402_0OHM]  255.49 148.95 0 bottom
PR1122  0_0402_5%  [R0402_0OHM]  255.49 148.06 0 bottom
PR1123  1.21K_0402_1%  [R_0402]  258.22 148.06 90 bottom
PR1124  100_0402_1%  [R_0402]  247.8 117.1 90 top
PR1125  100_0402_1%  [R_0402]  241.55 118.21 270 top
PR1126  0_0402_5%  [R0402_0OHM]  270.15 149.57 0 top
PR1127  1.05K_0402_1%  [R_0402]  268.38 148.69 0 top
PR1128  0_0402_5%  [R0402_0OHM]  271.05 147.78 90 top
PR1129  100_0402_1%  [R_0402]  246.92 117.1 90 top
PR1130  49.9_0402_1%  [R_0402]  256.79 147.72 180 top
PR1131  1K_0402_1%  [R_0402]  257.66 147.71 90 top
PR1132  27.4K_0402_1%  [R_0402]  260.53 145.05 180 bottom
PR1133  3.65K_0402_1%  [R_0402]  257.68 145.94 180 top
PR1134  49.9_0402_1%  [R_0402]  269.26 146.91 0 top
PR1135  27.4K_0402_1%  [R_0402]  267.07 146.71 180 bottom
PR1136  1K_0402_1%  [R_0402]  268.39 145.39 90 top
PR1137  3.65K_0402_1%  [R_0402]  271.94 146.04 270 top
PR1138  30.1K_0402_1%  [R_0402]  256.76 145.05 0 top
PR1139  11K_0402_1%  [R_0402]  268.95 144.2 270 top
PR1140  75K_0402_1%  [R_0402]  254.97 145.09 270 top
PR1141  75K_0402_1%  [R_0402]  269.84 143.29 90 top
PR1142  174K_0402_1%  [R_0402]  255.89 144.18 270 top
PR1143  88.7K_0603_1%  [R_0603]  255.16 140.79 0 top
PR1144  174K_0402_1%  [R_0402]  271.62 144.2 270 top
PR1145  61.9K_0603_1%  [R_0603]  268.86 141.11 270 top
PR1146  88.7K_0603_1%  [R_0603]  255.16 139.58 0 top
PR1148  88.7K_0603_1%  [R_0603]  255.16 138.36 0 top
PR1149  88.7K_0603_1%  [R_0603]  255.16 142.01 0 top
PR1150  1K_0402_1%  [R_0402]  261.46 138.59 90 top
PR1151  2.2_0603_5%  [R_0603]  262.53 137.93 90 top
PR1152  25.5K_0402_1%  [R_0402]  265.51 141.25 90 bottom
PR1153  24.9K_0402_1%  [R_0402]  266.4 141.25 90 bottom
PR1154  2.26K_0402_1%  [R_0402]  255.64 140.73 0 bottom
PR1155  100K_0402_1%  [R_0402]  260.69 141.42 90 bottom
PR1156  4.3K_0402_1%  [R_0402]  261.84 141.4 90 bottom
PR1157  24.9K_0402_1%  [R_0402]  262.71 141.41 90 bottom
PR1158  97.6K_0402_1%  [R_0402]  263.75 141.29 90 bottom
PR1160  2.26K_0402_1%  [R_0402]  268.86 140.91 270 bottom
PR1161  2.26K_0402_1%  [R_0402]  255.61 139.56 0 bottom
PR1163  2.26K_0402_1%  [R_0402]  255.66 138.37 0 bottom
PR1164  2.26K_0402_1%  [R_0402]  255.57 141.99 0 bottom
PR1165  0_0402_5%  [R0402_0OHM]  260.58 139.51 270 top
PR1166  0_0402_5%  [R0402_0OHM]  265.8 139.77 270 top
PR1167  61.9K_0402_1%  [R_0402]  260.6 137.16 0 top
PR1168  61.9K_0402_1%  [R_0402]  265.03 132.05 180 bottom
PR1169  10_0402_1%  [R_0402]  262.13 151.22 270 bottom
PR1170  1K_0402_1%  [R_0402]  267.23 138.86 90 top
PR1171  97.6K_0402_1%  [R_0402]  264.65 141.29 90 bottom
PR1198  0_0402_5%  [R0402_0OHM]  264.41 152.46 0 top
PR1199  45.3_0402_1%  [R_0402]  266.73 150.09 90 bottom
PR1200  2_0603_5%  [R_0603]  251.49 140.99 180 top
PR1201  3.9_0603_1%  [R_0603]  248.95 140.92 90 top
PR1202  2.2_1206_1%  [R_1206]  250.96 133.9 180 bottom
PR1203  10_0402_1%  [R_0402]  250.12 127.48 0 bottom
PR1204  3.9_0603_1%  [R_0603]  241.22 140.73 90 top
PR1205  2_0603_5%  [R_0603]  243.74 140.8 180 top
PR1206  2.2_1206_1%  [R_1206]  243.34 134.03 180 bottom
PR1207  10_0402_1%  [R_0402]  243.89 127.33 0 bottom
PR1208  2_0603_5%  [R_0603]  236.16 140.9 180 top
PR1209  3.9_0603_1%  [R_0603]  233.53 140.79 90 top
PR1210  2.2_1206_1%  [R_1206]  235.62 134 180 bottom
PR1211  3.9_0603_1%  [R_0603]  225.76 138.29 90 top
PR1212  2_0603_5%  [R_0603]  228.27 138.38 180 top
PR1213  2.2_1206_1%  [R_1206]  227.8 131.51 180 bottom
PR1214  10_0402_1%  [R_0402]  236.4 127.21 0 bottom
PR1215  10_0402_1%  [R_0402]  228.3 124.9 0 bottom
PR1216  0_0402_5%  [R_0402]  253.66 138.94 90 top
PR1217  0_0402_5%  [R_0402]  253.25 139.11 180 bottom
PR1218  0_0402_5%  [R_0402]  246.1 137.69 90 top
PR1219  0_0402_5%  [R_0402]  245.7 137.06 180 bottom
PR1220  0_0402_5%  [R_0402]  238.36 137.61 90 top
PR1221  0_0402_5%  [R_0402]  238.13 138.7 180 bottom
PR1222  0_0402_5%  [R_0402]  230.46 135.28 90 top
PR1223  0_0402_5%  [R_0402]  230.57 136.31 180 bottom
PR1700  2_0603_5%  [R_0603]  270.75 129.73 270 bottom
PR1701  3.9_0603_1%  [R_0603]  270.82 127.15 0 bottom
PR1702  2.2_1206_1%  [R_1206]  263.35 123.44 270 bottom
PR1703  10_0402_1%  [R_0402]  257.62 130.15 90 top
PR1800  3.9_0603_1%  [R_0603]  215.48 132.4 90 bottom
PR1801  2_0603_5%  [R_0603]  217.95 133.96 180 bottom
PR1802  2.2_1206_1%  [R_1206]  216.71 127.04 180 bottom
PR2100  300K_0402_1%  [R_0402]  37.51 10.51 180 top
PR2101  1M_0402_1%  [R_0402]  39.21 18.64 270 bottom
PR2104  300K_0402_1%  [R_0402]  38.65 18.64 180 top
PR2105  1M_0402_1%  [R_0402]  39.09 21.39 270 bottom
PR2106  0_0402_5%  [R0402_0OHM]  39.22 17.68 270 top
PR2108  100K_0402_1%  [R_0402]  35.12 16.09 180 top
PR2109  100K_0402_1%  [R_0402]  38.18 24.24 0 top
PR2134  100K_0402_1%  [R_0402]  35.75 10.51 180 top
PR2142  100K_0402_1%  [R_0402]  36.86 18.62 180 top
PR2150  0_0402_5%  [R0402_0OHM]  38.34 10.35 270 top
PR2163  100K_0402_5%  [R_0402]  48.57 23.73 270 top
PU100  -  [SY8288BRAC_QFN20_3X3]  111.59 5.8 90 top
PU101  -  [SY8288CRAC_QFN20_3X3]  70.23 14.48 180 bottom
PU200  -  [RT8207PGQW_WQFN20_3X3]  204.38 13.08 180 top
PU300  -  [NB681GD-Z_QFN13_2X3]  273.45 98.09 90 bottom
PU400  -  [G5719CRC1U_TDFN8_2X2]  283.85 45.09 0 top
PU500  -  [SY8288CRAC_QFN20_3X3]  308.74 37.33 90 top
PU501  -  [SY8288BRAC_QFN20_3X3]  310.04 27.44 90 top
PU700  BQ24780SRUYR_QFN28_4X4  [BQ24780RUYR_WQFN28_4X4]  288.67 32.35 270 top
PU800  -  [TPS51212DSCR_SON10_3X3]  154.72 11.55 90 top
PU900  -  [G5719CRC1U_TDFN8_2X2]  127.37 6.41 270 top
PU1100  -  [NCP81215DMNTXG_QFN52_6X6]  260.43 147.33 0 top
PU1200  NCP302045MNTXG_PQFN33_5X5  [NCP302045MNTXG_PQFN33_5X5-S]  251.84 139.25 180 top
PU1201  NCP302045MNTXG_PQFN33_5X5  [NCP302045MNTXG_PQFN33_5X5-S]  244.14 139.14 180 top
PU1202  NCP302045MN_PQFN33_5X5  [NCP302045MNTXG_PQFN33_5X5-S]  236.41 139.14 180 top
PU1203  NCP302045MN_PQFN33_5X5  [NCP302045MNTXG_PQFN33_5X5-S]  228.51 136.72 180 top
PU1700  NCP302045MN_PQFN33_5X5  [NCP302045MNTXG_PQFN33_5X5-S]  269.16 129.91 270 bottom
PU1800  NCP302045MN_PQFN33_5X5  [NCP302045MNTXG_PQFN33_5X5-S]  217.6 132.32 180 top
PWRSW1  @SHORT PADS~D  [SHORTPADS]  317.95 41.84 180 top
QA10  -  [L2N7002WT1G_SC-70-3]  352.75 15.14 270 bottom
QE2  -  [L2N7002DW1T1G_SC88-6]  118.1 19.11 270 top
QE3  -  [LMBT3904WT1G_SC70-3]  245.43 103.01 0 bottom
QE4  -  [LMBT3904WT1G_SC70-3]  156.71 28.88 270 top
QE6  -  [LMBT3904WT1G_SC70-3]  279.1 10.67 0 top
QE7  -  [LMBT3904WT1G_SC70-3]  68.82 40.02 0 bottom
QE11  -  [L2N7002WT1G_SC-70-3]  157.04 26.93 0 top
QE12  -  [L2N7002WT1G_SC-70-3]  150.84 33.62 90 top
QE15  -  [PJ2301_SOT23-3]  152.76 30.38 90 top
QE17  -  [L2N7002WT1G_SC-70-3]  152.48 27.04 270 top
QE26  -  [LMBT3904WT1G_SC70-3]  250.77 148.29 0 top
QE104  -  [LMBT3904WT1G_SC70-3]  198.06 54.05 0 top
QH4  -  [L2N7002DW1T1G_SC88-6]  162.39 31.21 180 top
QH6  -  [L2N7002WT1G_SC-70-3]  121.39 11.7 0 top
QH7  -  [PJ2301_SOT23-3]  127.5 10.61 90 top
QL1  -  [2N7002KDW_SOT363-6]  195.96 127.59 0 top
QL7  -  [L2N7002WT1G_SC-70-3]  198.25 131.53 90 top
QN1  -  [2N7002KDW_SOT363-6]  343.14 27.61 0 bottom
QR1  -  [L2N7002WT1G_SC-70-3]  31.63 9.76 270 bottom
QT1  -  [L2N7002WT1G_SC-70-3]  29.33 20.38 270 bottom
QT2  S TR AO7401 1P SC70-3  [SI1303DL-T1-E3_SOT323-3]  35.94 25.34 180 top
QT3  S TR AO7401 1P SC70-3  [SI1303DL-T1-E3_SOT323-3]  42.28 25.73 90 bottom
QT4  -  [2N7002KDW_SOT363-6]  36.86 26.17 180 bottom
QT5  -  [L2N7002WT1G_SC-70-3]  66 22.88 270 bottom
QT6  -  [L2N7002WT1G_SC-70-3]  71.63 26.19 0 top
QT7  -  [L2N7002WT1G_SC-70-3]  45.34 39.45 0 top
QT8  -  [L2N7002WT1G_SC-70-3]  71.59 22.67 0 bottom
QT9  -  [L2N7002WT1G_SC-70-3]  68.37 23.81 270 top
QT10  -  [EMB80P03JS_SOT-23-3]  36.18 7.68 180 bottom
QV1  -  [AO6405_TSOP6]  88.16 41.88 180 top
QV2  -  [L2N7002WT1G_SC-70-3]  82.53 58.83 0 bottom
QV7  -  [L2N7002WT1G_SC-70-3]  75.81 26.55 180 top
QV8  -  [PJ2301_SOT23-3]  79.03 27.28 180 top
QV23  -  [L2N7002DW1T1G_SC88-6]  87.47 31.4 180 top
QV30  -  [2N7002KDW_SOT363-6]  185.72 105.58 270 top
QV40  -  [L2N7002WT1G_SC-70-3]  187.96 84.71 0 top
QV41  -  [L2N7002WT1G_SC-70-3]  184.61 80.62 270 top
QV42  -  [L2N7002WT1G_SC-70-3]  187.27 94.51 0 top
QV43  -  [L2N7002WT1G_SC-70-3]  79.14 63.05 180 bottom
QV44  -  [L2N7002DW1T1G_SC88-6]  95.47 35.65 180 top
QZ1  -  [PJ2301_SOT23-3]  78.2 58.32 270 bottom
QZ3  -  [LMUN5111T1G_SC70-3]  135.59 8.59 180 top
QZ7  -  [L2N7002WT1G_SC-70-3]  316.13 47.54 0 top
QZ15  -  [L2N7002WT1G_SC-70-3]  140.05 34.79 270 top
QZ17  -  [L2N7002DW1T1G_SC88-6]  339.34 4.16 180 top
QZ18  -  [L2N7002DW1T1G_SC88-6]  338.04 4.16 0 bottom
QZ19  AOSP21357L_SO8  [Q_P_SO8]  95.08 15.09 270 top
QZ20  -  [DMN3150LW-7_SOT323-3]  92.02 9.52 0 top
QZ21  -  [L2N7002WT1G_SC-70-3]  297.4 57.33 90 top
QZ22  -  [LMBT3904WT1G_SC70-3]  138.07 9.78 0 top
R127  100K_0402_5%  [R_0402]  327.6 20.8 270 top
R128  100K_0402_5%  [R_0402]  207.29 126.38 0 top
R129  100K_0402_5%  [R_0402]  329.31 18.06 270 top
RA5  2.2K_0402_5%  [R_0402]  354.13 22.47 180 top
RA6  2.2K_0402_5%  [R_0402]  354.14 23.4 180 top
RA7  16.2_0402_1%  [R_0402]  352.05 21.27 180 top
RA8  16.2_0402_1%  [R_0402]  352.05 20.4 180 top
RA9  33_0402_5%  [R_0402]  341.35 18.9 0 top
RA12  1K_0402_5%  [R_0402]  350.83 30.07 0 bottom
RA13  1K_0402_5%  [R_0402]  353.02 30.07 0 bottom
RA14  22_0402_5%  [R_0402]  341.03 22.38 180 top
RA17  33_0402_5%  [R_0402]  341.05 20.01 180 top
RA18  10K_0402_5%  [R_0402]  340.69 24.44 90 top
RA44  100K_0402_5%  [R_0402]  348.34 29.28 270 bottom
RA48  0_0402_5%  [R0402_0OHM]  337 21.64 270 top
RA50  0_0402_5%  [R_0402]  337.47 26.52 0 top
RA52  100K_0402_5%  [R_0402]  340.12 23.55 0 top
RA201  0_0603_5%  [R0603_0OHM]  348.21 14.84 90 top
RA209  10K_0402_5%  [R_0402]  352.96 29.21 0 bottom
RA213  0_0402_5%  [R_0402]  353.51 26.19 90 bottom
RA214  10K_0402_5%  [R_0402]  352.68 26.19 90 bottom
RA219  10K_0402_5%  [R_0402]  349.91 14.93 90 bottom
RA220  100K_0402_5%  [R_0402]  350.77 16.09 270 top
RA221  0_0402_5%  [R0402_0OHM]  348.08 15.15 90 bottom
RA222  0_0402_5%  [R0402_0OHM]  355.72 25.65 180 top
RA223  0_0402_5%  [R0402_0OHM]  358.81 23.1 270 top
RA224  10K_0402_5%  [R_0402]  329.22 19.71 270 top
RA225  10K_0402_5%  [R_0402]  351.08 29.18 0 bottom
RA226  0_0402_5%  [R0402_0OHM]  350.24 28.8 180 bottom
RA227  0_0402_5%  [R0402_0OHM]  347.39 23.92 0 bottom
RA228  0_0402_5%  [R0402_0OHM]  358.75 15.19 90 top
RC1  24.9_0402_1%  [R_0402]  207.5 111.56 180 bottom
RC2  24.9_0402_1%  [R_0402]  221.49 83.23 90 bottom
RC5  121_0402_1%  [R_0402]  218.26 81.77 90 top
RC6  75_0402_1%  [R_0402]  219.28 81.77 90 top
RC7  100_0402_1%  [R_0402]  220.29 81.77 90 top
RC66  20_0402_5%  [R_0402]  214.14 111.15 180 top
RC71  1K_0402_5%  [R_0402]  196.62 90.96 90 bottom
RC74  10K_0402_5%  [R_0402]  163.95 36.29 0 top
RC75  10K_0402_5%  [R_0402]  170.07 17.06 270 bottom
RC78  60.4_0402_1%  [R_0402]  197.5 92.87 90 bottom
RC79  49.9_0402_1%  [R_0402]  266.11 106.28 180 top
RC80  1K_0402_5%  [R_0402]  199.86 115.84 180 bottom
RC83  1K_0402_5%  [R_0402]  268.17 107.94 180 top
RC84  499_0402_1%  [R_0402]  266.23 107.17 180 top
RC114  49.9_0402_1%  [R_0402]  262.33 105.22 0 top
RC115  2.2K_0402_5%  [R_0402]  278.87 92.32 180 top
RC121  1K_0402_5%  [R_0402]  286.35 76.86 90 top
RC122  0_0402_5%  [R_0402]  287.24 76.86 90 top
RC124  1K_0402_5%  [R_0402]  278.63 86.93 0 bottom
RC126  1K_0402_5%  [R_0402]  280.32 80.05 180 top
RC127  0_0402_5%  [R0402_0OHM]  279.2 99.1 180 top
RC128  1K_0402_5%  [R_0402]  169.39 64.05 225 bottom
RC129  0_0402_5%  [R_0402]  278.65 83.8 0 bottom
RC132  150_0402_5%  [R_0402]  278.51 92.28 0 bottom
RC133  1.5K_0402_5%  [R_0402]  278.65 82.91 0 bottom
RC135  51_0402_5%  [R_0402]  265.06 103.99 0 top
RC136  51_0402_5%  [R_0402]  276.91 96.27 180 top
RC137  3K_0402_5%  [R_0402]  276.9 94.4 180 top
RC138  51_0402_5%  [R_0402]  266.11 105.39 180 top
RC139  51_0402_5%  [R_0402]  283.1 99.09 90 top
RC143  0_0402_5%  [R0402_0OHM]  283.99 99.09 90 top
RC144  0_0402_5%  [R0402_0OHM]  276.9 93.32 180 top
RC152  56.2_0402_1%  [R_0402]  260.95 120.07 270 bottom
RC153  220_0402_5%  [R_0402]  261.84 120.07 270 bottom
RC157  100_0402_5%  [R_0402]  262.78 119.23 0 bottom
RC166  1K_0402_5%  [R_0402]  283.1 100.87 0 top
RC168  20_0402_5%  [R_0402]  266.23 109.58 180 top
RC169  0_0402_5%  [R0402_0OHM]  198.91 117.66 0 bottom
RC171  0_0402_5%  [R_0402]  262.27 82.45 0 bottom
RC177  30_0402_5%  [R_0402]  225.75 104.66 270 bottom
RC178  0_0402_5%  [R0402_0OHM]  214.14 112.09 180 top
RC179  0_0402_5%  [R0402_0OHM]  214.15 113.07 180 top
RC181  1K_0402_5%  [R_0402]  281.35 83.93 180 bottom
RC216  0_0603_5%  [R0603_0OHM]  268.76 104.37 180 top
RC217  0_0402_5%  [R_0402]  278.51 91.39 0 bottom
RC218  150_0402_5%  [R_0402]  277.66 92.05 270 bottom
RC219  10K_0402_5%  [R_0402]  277.64 89.39 90 bottom
RC221  49.9_0402_1%  [R_0402]  254.55 148.08 90 bottom
RC228  0_0402_5%  [R0402_0OHM]  279.2 98.18 180 top
RC229  0_0402_5%  [R0402_0OHM]  279.29 95.83 180 top
RC230  0_0402_5%  [R0402_0OHM]  276.9 95.29 180 top
RC239  0_0402_5%  [R_0402]  262.33 106.18 0 top
RC240  0_0402_5%  [R_0402]  262.33 107.07 0 top
RC241  1.5K_0402_5%  [R_0402]  278.53 89.13 0 bottom
RC304  0_0402_5%  [R0402_0OHM]  189.84 86.11 90 top
RC314  0_0402_5%  [R0402_0OHM]  261.46 106.61 270 top
RC315  0_0402_5%  [R0402_0OHM]  283.52 77.73 270 bottom
RC319  0_0402_5%  [R0402_0OHM]  266.23 110.47 180 top
RC321  1K_0402_5%  [R_0402]  280.2 80.5 180 bottom
RC322  1K_0402_5%  [R_0402]  264.08 101.74 180 top
RC323  1K_0402_5%  [R_0402]  262.02 97.26 0 top
RC324  1K_0402_5%  [R_0402]  262.19 100.41 0 top
RC325  1K_0402_5%  [R_0402]  261.38 101.78 0 top
RC326  0_0402_5%  [R0402_0OHM]  194.11 98.72 270 top
RC366  15_0402_5%  [R_0402]  164.48 22.08 270 bottom
RC367  15_0402_5%  [R_0402]  165.36 21.78 270 bottom
RC368  15_0402_5%  [R_0402]  166.24 21.78 270 bottom
RC369  15_0402_5%  [R_0402]  167.1 22.07 270 bottom
RC370  10K_0201_5%  [R_0201]  173.51 31.97 180 bottom
RC436  1K_0402_5%  [R_0402]  281.35 83.04 180 bottom
RC437  1K_0402_5%  [R_0402]  263.33 104.25 0 top
RC438  1K_0402_5%  [R_0402]  265.36 101.92 270 top
RC439  1K_0402_5%  [R_0402]  266.31 102.85 180 top
RC440  1K_0402_5%  [R_0402]  263.16 102.85 0 top
RC441  1K_0402_5%  [R_0402]  262.3 102.85 180 top
RC442  1K_0402_5%  [R_0402]  262.02 96.37 0 top
RC443  1K_0402_5%  [R_0402]  262.02 98.4 0 top
RC444  10K_0402_5%  [R_0402]  178.62 17.16 270 bottom
RC560  0_0402_5%  [R_0402]  162.11 29.62 180 bottom
RC561  0_0402_5%  [R_0402]  162.1 28.72 180 bottom
RC562  0_0201_5%  [R_0201]  196.81 88.92 90 top
RD4  470_0402_1%  [R_0402]  251.46 66.58 270 bottom
RD7  1K_0402_5%  [R_0402]  242.45 66.71 270 bottom
RD8  1K_0402_5%  [R_0402]  230.81 34.38 0 bottom
RD9  2_0402_1%  [R_0402]  234.37 30.82 0 bottom
RD10  2_0402_1%  [R_0402]  233.51 31.71 180 bottom
RD11  1K_0402_5%  [R_0402]  231.73 30.82 180 bottom
RD12  24.9_0402_1%  [R_0402]  236.22 31.79 270 bottom
RD14  0_0402_5%  [R_0402]  197.64 60.88 180 bottom
RD15  0_0402_5%  [R_0402]  198 62.07 180 bottom
RD16  0_0603_5%  [R0603_0OHM]  212.71 32.82 0 bottom
RD17  330K_0402_5%  [R_0402]  282.07 71.05 90 bottom
RD18  0_0402_5%  [R_0402]  195.71 58.49 180 bottom
RD21  1K_0402_5%  [R_0402]  240.67 66.71 270 bottom
RD22  0_0402_5%  [R_0402]  201.46 36.2 0 bottom
RD23  0_0402_5%  [R_0402]  201.5 41.48 0 bottom
RD24  0_0402_5%  [R_0402]  229.33 29.89 180 bottom
RD29  1K_0402_5%  [R_0402]  242.19 63.26 90 bottom
RD30  1K_0402_5%  [R_0402]  271.44 79.35 180 bottom
RD31  2_0402_1%  [R_0402]  271.42 83.79 180 bottom
RD32  1K_0402_5%  [R_0402]  270.52 81.13 0 bottom
RD33  24.9_0402_1%  [R_0402]  273.27 82.96 90 bottom
RD34  1K_0402_5%  [R_0402]  235.59 63.13 90 bottom
RD36  0_0402_5%  [R_0402]  234.7 63.13 90 bottom
RD37  1K_0402_5%  [R_0402]  236.54 64.08 0 bottom
RD40  0_0402_5%  [R_0402]  197.67 56.77 0 bottom
RD42  0_0402_5%  [R_0402]  202.17 60.18 270 bottom
RD43  0_0402_5%  [R_0402]  199.54 54.92 180 bottom
RD45  1K_0402_5%  [R_0402]  241.56 66.71 270 bottom
RD46  0_0402_5%  [R_0402]  201.43 55.39 0 bottom
RD48  0_0402_5%  [R_0402]  200.47 54.42 0 bottom
RD51  0_0402_5%  [R_0402]  201.93 57.43 90 bottom
RD76  0_0402_5%  [R0402_0OHM]  251.54 64.22 180 bottom
RD77  0_0402_5%  [R0402_0OHM]  250.52 65.62 180 bottom
RD78  0_0402_5%  [R0402_0OHM]  195.71 59.42 180 bottom
RD79  0_0402_5%  [R0402_0OHM]  197.63 59.92 180 bottom
RD80  0_0402_5%  [R0402_0OHM]  197.99 62.96 180 bottom
RD81  0_0402_5%  [R0402_0OHM]  201.46 37.08 0 bottom
RD82  0_0402_5%  [R0402_0OHM]  201.5 42.38 0 bottom
RD83  0_0402_5%  [R0402_0OHM]  229.31 28.98 180 bottom
RD84  0_0402_5%  [R0402_0OHM]  233.77 67.07 0 bottom
RD85  0_0402_5%  [R0402_0OHM]  201.28 60.17 270 bottom
RD86  0_0402_5%  [R0402_0OHM]  199.55 55.81 180 bottom
RD87  0_0402_5%  [R0402_0OHM]  197.66 57.66 0 bottom
RD88  0_0402_5%  [R0402_0OHM]  200.99 57.43 90 bottom
RD89  0_0402_5%  [R0402_0OHM]  201.41 56.36 0 bottom
RD90  0_0402_5%  [R0402_0OHM]  200.47 53.54 0 bottom
RD92  0_0603_5%  [R0603_0OHM]  202.11 45.53 180 bottom
RD93  0_0603_5%  [R0603_0OHM]  196.75 55.14 270 bottom
RD94  0_0603_5%  [R0603_0OHM]  202.54 57.56 180 top
RE8  100K_0402_5%  [R_0402]  141.89 21.66 0 top
RE10  100K_0402_5%  [R_0402]  141.37 25.5 0 bottom
RE11  100K_0402_5%  [R_0402]  129.33 33.6 180 bottom
RE12  100K_0402_5%  [R_0402]  129.99 22.58 180 bottom
RE20  100K_0402_5%  [R_0402]  127.68 17.52 180 top
RE21  10K_0402_5%  [R_0402]  138.84 30.5 90 bottom
RE25  100K_0402_5%  [R_0402]  138.61 16.83 180 top
RE26  10_0402_5%  [R_0402]  138.61 15.94 180 top
RE30  0_0402_5%  [R0402_0OHM]  51.89 6.74 180 bottom
RE31  100K_0402_5%  [R_0402]  130.24 39.02 270 bottom
RE32  0_0402_5%  [R0402_0OHM]  131.03 31.86 90 bottom
RE33  1K_0402_5%  [R_0402]  129.35 38.1 90 bottom
RE35  10K_0402_5%  [R_0402]  140.79 17.17 270 top
RE37  2.2K_0402_5%  [R_0402]  128.78 17.22 270 top
RE38  10K_0402_5%  [R_0402]  141.84 18.89 0 top
RE43  2.2K_0402_5%  [R_0402]  129.67 17.22 270 top
RE55  100K_0402_5%  [R_0402]  129.61 31.78 90 bottom
RE56  10K_0402_5%  [R_0402]  128.33 25.06 180 bottom
RE57  1K_0402_5%  [R_0402]  127.56 31.27 90 bottom
RE58  100K_0402_5%  [R_0402]  128.45 31.27 90 bottom
RE59  0_0402_5%  [R0402_0OHM]  142.34 24.48 180 bottom
RE60  33_0402_5%  [R_0402]  144.79 23.22 0 top
RE63  100K_0402_5%  [R_0402]  145.3 28.44 270 top
RE64  300_0402_5%  [R_0402]  132.03 13.98 270 bottom
RE65  100_0402_1%  [R_0402]  143.01 28.66 270 top
RE67  10K_0402_5%  [R_0402]  116.87 19.6 180 top
RE68  100K_0402_5%  [R_0402]  119.39 16.55 180 top
RE69  8.2K_0402_5%  [R_0402]  155.54 27.97 90 top
RE70  2.2K_0402_5%  [R_0402]  158.83 26.26 90 top
RE71  10_0402_1%  [R_0402]  51.13 3.54 0 bottom
RE72  10K_0402_5%  [R_0402]  49.76 5.76 0 bottom
RE73  10K_0402_5%  [R_0402]  63.41 5.82 180 bottom
RE74  10K_0402_5%  [R_0402]  63.41 4.93 180 bottom
RE75  100K_0402_5%  [R_0402]  52.97 6.9 270 bottom
RE77  1.58K_0402_1%  [R_0402]  136.78 29.43 0 bottom
RE79  2K_0402_5%  [R_0402]  144.62 26.17 270 top
RE83  100K_0402_5%  [R_0402]  142.06 25.49 0 top
RE84  100K_0402_5%  [R_0402]  137.5 16.11 0 bottom
RE86  10K_0402_5%  [R_0402]  53.91 5.99 90 bottom
RE90  0_0402_5%  [R0402_0OHM]  158.84 25.37 270 top
RE91  100K_0402_5%  [R_0402]  142.04 30.11 0 bottom
RE93  100K_0201_5%  [R_0201]  153.76 32.74 90 top
RE94  75_0402_5%  [R_0402]  149.7 33.63 90 top
RE95  100K_0402_5%  [R_0402]  134.27 16.12 90 top
RE274  0_0402_5%  [R_0402]  126.82 20.32 0 top
RE275  0_0402_5%  [R0402_0OHM]  141.66 16.26 90 top
RE280  0_0402_5%  [R_0402]  160.71 18.7 0 top
RE288  100_0402_5%  [R_0402]  142.06 26.38 0 top
RE290  0_0402_5%  [R0402_0OHM]  132.48 31.66 90 top
RE292  0_0402_5%  [R_0402]  161.62 19.57 180 top
RE300  8.2K_0402_5%  [R_0402]  140 20.78 180 bottom
RE302  2.2K_0402_5%  [R_0402]  131.26 29.41 90 bottom
RE303  2.2K_0402_5%  [R_0402]  130.33 29.01 90 bottom
RE304  0_0402_5%  [R_0402]  163 19.33 270 top
RE306  0_0402_5%  [R_0402]  63.41 6.71 180 bottom
RE312  300_0402_5%  [R_0402]  132.25 15.59 180 bottom
RE313  10K_0402_5%  [R_0402]  132.26 16.46 180 bottom
RE314  100_0402_1%  [R_0402]  125.76 27.55 270 top
RE318  0_0402_5%  [R0402_0OHM]  126.73 25.06 0 top
RE342  10K_0402_5%  [R_0402]  114.53 12.63 180 top
RE343  33K_0402_5%  [R_0402]  120.9 26.01 180 bottom
RE349  43K_0402_1%  [R_0402]  132.24 16.48 90 top
RE350  33_0402_5%  [R_0402]  135.19 21.58 90 bottom
RE362  100K_0402_5%  [R_0402]  124.67 34.34 0 bottom
RE365  100K_0402_5%  [R_0402]  142.13 30.22 0 top
RE505  100K_0402_5%  [R_0402]  123.74 34.33 180 bottom
RE506  0_0402_5%  [R0402_0OHM]  135.18 17.04 270 top
RE507  100K_0402_5%  [R_0402]  133.38 31.65 90 top
RE508  100K_0402_5%  [R_0402]  129.39 27.28 180 bottom
RE526  10K_0402_5%  [R_0402]  142.47 26.43 180 bottom
